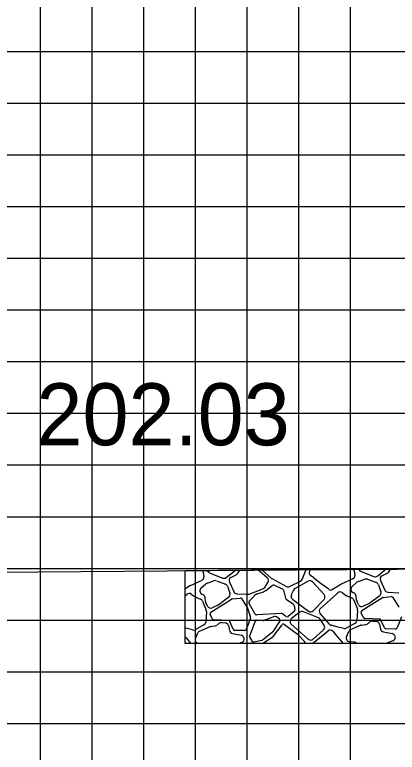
# Model space of a CAD drawing. Extents: x 852922 to 853266, y 364785 to 365005.
# Drawn here: x 853025.74 to 853033.15, y 364866.67 to 364880.95 of the extents above; entities that cross this region are included whole.
import ezdxf

# ---------------------------------------------------------------- set-up
doc = ezdxf.new("R2010")
doc.units = 0
for name, color, linetype in [('D_Roadway_FinishedGrade', 7, 'Continuous'), ('D_Text_Standard', 7, 'Continuous'), ('MAJOR', 7, 'Continuous'), ('MINOR', 7, 'Continuous'), ('S_Roadway_Centerline', 7, 'Continuous')]:
    doc.layers.add(name, color=color, linetype=linetype)

msp = doc.modelspace()

# ---------------------------------------------------------------- linework, layer by layer
at = {"layer": 'D_Roadway_FinishedGrade'}
for p, q in [((853029.394, 364870.158), (853029.404, 364870.066)), ((853029.466, 364870.193), (853029.503, 364870.157)), ((853029.526, 364870.142), (853029.772, 364870.044)), ((853029.84, 364870.055), (853030.016, 364870.198)), ((853030.097, 364870.199), (853030.048, 364870.126)), ((853030.632, 364870.047), (853030.45, 364870.203)), ((853030.527, 364870.204), (853030.71, 364870.043)), ((853031.308, 364870.019), (853031.389, 364870.212)), ((853031.459, 364870.19), (853031.477, 364870.213)), ((853032.319, 364870.187), (853032.328, 364870.096)), ((853032.391, 364870.222), (853032.428, 364870.186)), ((853032.45, 364870.171), (853032.696, 364870.073)), ((853032.765, 364870.084), (853032.941, 364870.228)), ((853033.022, 364870.229), (853032.973, 364870.155)), ((853030.023, 364870.103), (853029.931, 364870.056)), ((853030.723, 364870.035), (853031.004, 364869.884)), ((853031.532, 364870.047), (853031.471, 364870.094)), ((853031.653, 364869.95), (853031.532, 364870.046)), ((853032.288, 364870.027), (853032.066, 364869.925)), ((853032.392, 364869.976), (853032.525, 364870.022)), ((853032.572, 364870.022), (853032.746, 364869.957)), ((853032.947, 364870.132), (853032.856, 364870.085)), ((853029.134, 364869.892), (853029.047, 364869.839)), ((853029.364, 364869.997), (853029.141, 364869.896)), ((853029.349, 364869.848), (853029.444, 364869.933)), ((853029.468, 364869.947), (853029.601, 364869.993)), ((853029.647, 364869.992), (853029.822, 364869.927)), ((853029.862, 364869.886), (853029.909, 364869.752)), ((853029.9, 364869.967), (853029.983, 364869.782)), ((853030.583, 364869.863), (853030.645, 364869.957)), ((853030.605, 364869.805), (853030.731, 364869.902)), ((853030.766, 364869.906), (853030.929, 364869.836)), ((853031.066, 364869.883), (853031.275, 364869.984)), ((853031.424, 364869.984), (853031.171, 364869.841)), ((853031.732, 364869.725), (853031.508, 364869.97)), ((853031.823, 364869.827), (853031.655, 364869.948)), ((853031.972, 364869.868), (853031.898, 364869.824)), ((853032.059, 364869.921), (853031.972, 364869.868)), ((853032.274, 364869.878), (853032.369, 364869.963)), ((853032.787, 364869.915), (853032.834, 364869.781)), ((853032.825, 364869.996), (853032.908, 364869.811)), ((853029.047, 364869.839), (853029.044, 364869.837)), ((853029.048, 364869.705), (853029.076, 364869.729)), ((853029.161, 364869.735), (853029.24, 364869.68)), ((853029.394, 364869.721), (853029.364, 364869.736)), ((853030.043, 364869.742), (853030.255, 364869.732)), ((853030.282, 364869.736), (853030.549, 364869.836)), ((853030.44, 364869.738), (853030.559, 364869.78)), ((853030.949, 364869.813), (853030.989, 364869.656)), ((853031.143, 364869.812), (853031.099, 364869.722)), ((853031.664, 364869.457), (853031.973, 364869.734)), ((853031.973, 364869.734), (853032.001, 364869.759)), ((853032.085, 364869.764), (853032.164, 364869.709)), ((853032.318, 364869.75), (853032.288, 364869.766)), ((853032.967, 364869.771), (853033.18, 364869.761)), ((853029.044, 364869.7), (853029.048, 364869.705)), ((853029.252, 364869.673), (853029.342, 364869.635)), ((853029.378, 364869.599), (853029.453, 364869.421)), ((853029.438, 364869.59), (853029.43, 364869.667)), ((853029.542, 364869.388), (853029.938, 364869.637)), ((853029.886, 364869.675), (853029.703, 364869.534)), ((853029.953, 364869.642), (853030.109, 364869.656)), ((853030.141, 364869.64), (853030.255, 364869.451)), ((853030.284, 364869.595), (853030.371, 364869.691)), ((853031.002, 364869.637), (853031.138, 364869.539)), ((853031.12, 364869.638), (853031.434, 364869.403)), ((853031.525, 364869.411), (853031.732, 364869.633)), ((853032.177, 364869.702), (853032.266, 364869.664)), ((853032.302, 364869.628), (853032.378, 364869.451)), ((853032.363, 364869.62), (853032.355, 364869.696)), ((853032.398, 364869.533), (853032.368, 364869.599)), ((853032.466, 364869.417), (853032.863, 364869.666)), ((853032.811, 364869.704), (853032.628, 364869.563)), ((853032.878, 364869.671), (853033.033, 364869.686)), ((853033.066, 364869.669), (853033.179, 364869.481)), ((853029.473, 364869.503), (853029.444, 364869.57)), ((853029.69, 364869.526), (853029.564, 364869.469)), ((853030.258, 364869.444), (853030.308, 364869.286)), ((853030.4, 364869.349), (853030.28, 364869.555)), ((853031.152, 364869.517), (853031.167, 364869.428)), ((853032.614, 364869.555), (853032.488, 364869.498)), ((853029.459, 364869.389), (853029.443, 364869.193)), ((853029.567, 364869.257), (853029.528, 364869.346)), ((853030.905, 364869.361), (853030.432, 364869.332)), ((853030.771, 364869.301), (853030.569, 364869.223)), ((853030.869, 364869.254), (853030.802, 364869.298)), ((853030.995, 364869.303), (853030.927, 364869.354)), ((853031.154, 364869.395), (853031.037, 364869.304)), ((853031.265, 364869.386), (853031.1, 364869.26)), ((853031.628, 364869.272), (853031.333, 364869.394)), ((853031.837, 364869.152), (853031.657, 364869.362)), ((853032.383, 364869.418), (853032.367, 364869.222)), ((853032.491, 364869.286), (853032.453, 364869.375)), ((853033.232, 364869.293), (853033.149, 364869.08)), ((853029.879, 364869.222), (853029.596, 364869.236)), ((853029.66, 364869.134), (853029.697, 364869.167)), ((853029.748, 364869.183), (853029.821, 364869.176)), ((853029.976, 364869.053), (853029.909, 364869.202)), ((853030.307, 364869.263), (853030.224, 364869.05)), ((853030.397, 364869.21), (853030.291, 364868.923)), ((853030.554, 364869.221), (853030.432, 364869.232)), ((853030.767, 364869.034), (853030.879, 364869.207)), ((853030.967, 364869.147), (853031.236, 364868.946)), ((853031.096, 364869.155), (853031.428, 364868.861)), ((853031.734, 364869.133), (853031.659, 364869.247)), ((853032.332, 364869.168), (853032.162, 364869.075)), ((853032.457, 364869.135), (853032.549, 364869.147)), ((853032.804, 364869.252), (853032.521, 364869.265)), ((853032.584, 364869.163), (853032.622, 364869.196)), ((853032.673, 364869.212), (853032.746, 364869.206)), ((853032.806, 364869.153), (853032.828, 364869.056)), ((853032.901, 364869.082), (853032.833, 364869.232)), ((853029.055, 364869.073), (853029.044, 364869.076)), ((853029.188, 364869.04), (853029.055, 364869.073)), ((853029.407, 364869.139), (853029.238, 364869.046)), ((853029.323, 364869.018), (853029.515, 364869.101)), ((853029.533, 364869.105), (853029.624, 364869.118)), ((853029.882, 364869.124), (853029.904, 364869.027)), ((853030.192, 364869.029), (853030.007, 364869.033)), ((853030.542, 364868.848), (853030.76, 364869.026)), ((853030.75, 364868.914), (853030.919, 364869.14)), ((853031.508, 364868.779), (853031.81, 364869.023)), ((853031.519, 364868.861), (853031.723, 364869.044)), ((853031.979, 364869.103), (853031.872, 364869.13)), ((853031.905, 364869.014), (853031.981, 364868.923)), ((853032.113, 364869.069), (853031.979, 364869.103)), ((853032.167, 364868.906), (853032.211, 364869.012)), ((853032.247, 364869.048), (853032.439, 364869.13)), ((853032.882, 364869.004), (853033.053, 364868.971)), ((853033.116, 364869.058), (853032.931, 364869.062)), ((853029.044, 364868.909), (853029.057, 364868.894)), ((853029.057, 364868.894), (853029.153, 364868.779)), ((853029.242, 364868.877), (853029.287, 364868.982)), ((853029.957, 364868.975), (853030.128, 364868.942)), ((853030.182, 364868.891), (853030.184, 364868.88)), ((853030.294, 364868.894), (853030.334, 364868.827)), ((853030.538, 364868.779), (853030.741, 364868.905)), ((853031.24, 364868.942), (853031.357, 364868.818)), ((853031.981, 364868.923), (853032.102, 364868.779)), ((853033.106, 364868.92), (853033.109, 364868.909)), ((853029.334, 364868.779), (853029.298, 364868.782)), ((853030.141, 364868.799), (853030.086, 364868.779)), ((853030.301, 364868.779), (853030.314, 364868.784)), ((853030.347, 364868.781), (853030.349, 364868.779)), ((853030.37, 364868.811), (853030.526, 364868.841)), ((853032.325, 364868.802), (853032.223, 364868.812)), ((853033.066, 364868.828), (853032.93, 364868.779))]:
    msp.add_line(p, q, dxfattribs=at)
msp.add_lwpolyline([(853038.044, 364868.779), (853029.044, 364868.779), (853029.044, 364870.189), (853038.044, 364870.279)], dxfattribs=at)
for centre, radius, start, end in [((853029.326, 364870.151), 0.0684, 5.7687, 37.1559), ((853029.551, 364870.206), 0.0684, 225.5742, 248.268), ((853031.513, 364870.148), 0.0684, 142.5272, 231.9144), ((853032.251, 364870.18), 0.0684, 5.7687, 37.1559), ((853032.476, 364870.235), 0.0684, 225.5742, 248.268), ((853032.916, 364870.193), 0.0684, 297.1393, 326.3585), ((853029.335, 364870.059), 0.0684, 294.5367, 5.7687), ((853029.797, 364870.108), 0.0684, 248.268, 309.234), ((853029.962, 364869.995), 0.0684, 117.1393, 204.3237), ((853029.992, 364870.164), 0.0684, 297.1393, 326.3585), ((853030.588, 364869.995), 0.0684, 326.5778, 49.4679), ((853030.755, 364870.095), 0.0684, 228.8154, 241.8683), ((853031.245, 364870.046), 0.0684, 295.9781, 337.2187), ((853031.49, 364869.993), 0.0684, 51.4804, 51.9144), ((853032.26, 364870.089), 0.0684, 294.5367, 5.7687), ((853032.548, 364869.958), 0.0684, 69.6007, 109.0092), ((853032.721, 364870.137), 0.0684, 248.268, 309.234), ((853032.887, 364870.024), 0.0684, 117.1393, 204.3237), ((853029.17, 364869.833), 0.0684, 114.5367, 121.2249), ((853029.49, 364869.882), 0.0684, 109.0092, 131.7602), ((853029.623, 364869.928), 0.0684, 69.6007, 109.0092), ((853029.798, 364869.863), 0.0684, 19.3156, 69.6007), ((853030.526, 364869.9), 0.0684, 290.4998, 326.5778), ((853030.752, 364869.875), 0.0342, 66.7141, 127.3386), ((853031.036, 364869.944), 0.0684, 241.8683, 295.9781), ((853031.458, 364869.924), 0.0684, 42.4077, 119.3317), ((853031.695, 364870.004), 0.0684, 231.4804, 234.0454), ((853032.094, 364869.863), 0.0684, 114.5367, 121.2249), ((853032.319, 364869.827), 0.0684, 131.7602, 242.8748), ((853032.414, 364869.912), 0.0684, 109.0092, 131.7602), ((853032.722, 364869.893), 0.0684, 19.3156, 69.6007), ((853029.122, 364869.678), 0.0684, 55.3566, 131.8312), ((853029.395, 364869.797), 0.0684, 131.7602, 242.8748), ((853029.362, 364869.66), 0.0684, 5.7687, 62.8748), ((853029.845, 364869.729), 0.0684, 307.5941, 19.3156), ((853030.046, 364869.81), 0.0684, 204.3237, 267.3497), ((853030.258, 364869.8), 0.0684, 267.3497, 290.4998), ((853030.498, 364869.577), 0.171, 109.7079, 137.8958), ((853030.501, 364869.941), 0.171, 289.7079, 307.3386), ((853030.916, 364869.804), 0.0342, 14.335, 66.7141), ((853031.161, 364869.692), 0.0684, 154.0674, 233.2109), ((853031.204, 364869.782), 0.0684, 119.3317, 154.0674), ((853031.682, 364869.679), 0.0684, 317.0063, 42.4077), ((853031.863, 364869.882), 0.0684, 234.0454, 301.2249), ((853032.046, 364869.708), 0.0684, 55.3566, 131.8312), ((853032.287, 364869.69), 0.0684, 5.7687, 62.8748), ((853032.769, 364869.759), 0.0684, 307.5941, 19.3156), ((853032.97, 364869.84), 0.0684, 204.3237, 267.3497), ((853029.279, 364869.736), 0.0684, 235.3566, 246.9448), ((853029.315, 364869.572), 0.0684, 23.0537, 66.9449), ((853029.506, 364869.597), 0.0684, 185.7687, 203.9594), ((853029.956, 364869.608), 0.0342, 95.2411, 122.1256), ((853030.112, 364869.622), 0.0342, 31.0845, 95.2411), ((853030.309, 364869.572), 0.0342, 137.8958, 210.3662), ((853031.022, 364869.665), 0.0342, 194.335, 234.2606), ((853032.203, 364869.765), 0.0684, 235.3566, 246.9449), ((853032.239, 364869.601), 0.0684, 23.0537, 66.9449), ((853032.431, 364869.627), 0.0684, 185.7687, 203.9594), ((853032.881, 364869.637), 0.0342, 95.2411, 122.1256), ((853033.036, 364869.652), 0.0342, 31.0845, 95.2411), ((853029.536, 364869.531), 0.0684, 203.9594, 294.4344), ((853029.661, 364869.588), 0.0684, 294.4344, 307.5941), ((853030.225, 364869.434), 0.0342, 17.5017, 31.0845), ((853031.118, 364869.511), 0.0342, 9.3204, 54.2606), ((853031.709, 364869.406), 0.0684, 131.8312, 220.5318), ((853032.315, 364869.424), 0.0684, 355.3798, 23.0537), ((853032.46, 364869.56), 0.0684, 203.9594, 294.4344), ((853032.586, 364869.618), 0.0684, 294.4344, 307.5941), ((853029.39, 364869.395), 0.0684, 355.3798, 23.0537), ((853029.56, 364869.359), 0.0342, 122.1256, 203.1941), ((853030.275, 364869.276), 0.0342, 338.7728, 17.5017), ((853030.43, 364869.366), 0.0342, 210.3662, 273.5646), ((853030.783, 364869.269), 0.0342, 56.8842, 111.0577), ((853030.907, 364869.327), 0.0342, 53.0056, 93.5646), ((853031.016, 364869.331), 0.0342, 233.0056, 308.109), ((853031.133, 364869.422), 0.0342, 308.109, 9.3204), ((853031.307, 364869.331), 0.0684, 67.552, 127.1813), ((853031.475, 364869.457), 0.0684, 233.2109, 317.0063), ((853032.484, 364869.388), 0.0342, 122.1256, 203.1941), ((853032.523, 364869.299), 0.0342, 203.1941, 267.2468), ((853029.375, 364869.199), 0.0684, 298.6467, 355.3798), ((853029.598, 364869.27), 0.0342, 203.1941, 267.2468), ((853029.742, 364869.115), 0.0684, 84.8636, 130.9388), ((853029.815, 364869.108), 0.0684, 12.9816, 84.8636), ((853029.878, 364869.188), 0.0342, 24.3237, 87.2468), ((853030.429, 364869.198), 0.0342, 85.002, 159.5814), ((853030.557, 364869.255), 0.0342, 265.002, 291.0577), ((853030.85, 364869.225), 0.0342, 326.8842, 56.8842), ((853030.947, 364869.12), 0.0342, 53.1689, 143.1689), ((853031.142, 364869.206), 0.0684, 127.1813, 228.4518), ((853031.602, 364869.209), 0.0684, 33.5368, 67.552), ((853031.889, 364869.196), 0.0684, 220.5318, 255.8307), ((853032.299, 364869.228), 0.0684, 298.6467, 355.3798), ((853032.539, 364869.215), 0.0684, 277.6992, 310.9388), ((853032.667, 364869.144), 0.0684, 84.8636, 130.9388), ((853032.739, 364869.138), 0.0684, 12.9816, 84.8636), ((853032.802, 364869.218), 0.0342, 24.3237, 87.2468), ((853029.205, 364869.106), 0.0684, 255.8307, 298.6467), ((853029.35, 364868.955), 0.0684, 113.1941, 156.8921), ((853029.542, 364869.038), 0.0684, 97.6992, 113.1941), ((853029.615, 364869.186), 0.0684, 277.6992, 310.9388), ((853029.971, 364869.042), 0.0684, 192.9816, 258.9406), ((853030.007, 364869.067), 0.0342, 204.3237, 268.6964), ((853030.193, 364869.063), 0.0342, 268.6964, 338.7728), ((853030.738, 364869.053), 0.0342, 309.3484, 326.8842), ((853031.677, 364869.095), 0.0684, 311.8205, 33.5368), ((853031.853, 364868.97), 0.0684, 40.0454, 128.9472), ((853032.13, 364869.135), 0.0684, 255.8307, 298.6467), ((853032.274, 364868.985), 0.0684, 113.1941, 156.8921), ((853032.466, 364869.067), 0.0684, 97.6992, 113.1941), ((853032.895, 364869.071), 0.0684, 192.9816, 258.9406), ((853032.932, 364869.096), 0.0342, 204.3237, 268.6964), ((853033.117, 364869.092), 0.0342, 268.6964, 338.7728), ((853029.305, 364868.85), 0.0684, 156.8921, 264.52), ((853030.115, 364868.874), 0.0684, 13.7083, 78.9406), ((853030.118, 364868.863), 0.0684, 289.9802, 13.7083), ((853030.323, 364868.911), 0.0342, 159.5814, 211.2249), ((853030.722, 364868.934), 0.0342, 301.9472, 323.1689), ((853031.215, 364868.919), 0.0342, 43.3633, 53.1689), ((853031.473, 364868.912), 0.0684, 228.4518, 311.8205), ((853032.23, 364868.88), 0.0684, 156.8921, 264.52), ((853033.04, 364868.904), 0.0684, 13.7083, 78.9406), ((853033.042, 364868.893), 0.0684, 289.9802, 13.7083), ((853030.327, 364868.753), 0.0342, 55.0366, 111.7683), ((853030.363, 364868.844), 0.0342, 211.2249, 280.7782), ((853030.52, 364868.874), 0.0342, 280.7782, 309.3484), ((853031.307, 364868.771), 0.0684, 6.2815, 43.3633), ((853032.319, 364868.734), 0.0684, 41.354, 84.52)]:
    msp.add_arc(centre, radius, start, end, dxfattribs=at)
at = {"layer": 'MAJOR'}
for p, q in [((853028.244, 364858.233), (853028.244, 364893.233)), ((852948.244, 364878.233), (853228.244, 364878.233)), ((852948.244, 364873.233), (853228.244, 364873.233)), ((852948.244, 364868.233), (853228.244, 364868.233))]:
    msp.add_line(p, q, dxfattribs=at)
at = {"layer": 'MINOR'}
for p, q in [((853026.244, 364858.233), (853026.244, 364893.233)), ((853027.244, 364858.233), (853027.244, 364893.233)), ((853029.244, 364858.233), (853029.244, 364893.233)), ((853030.244, 364858.233), (853030.244, 364893.233)), ((853031.244, 364858.233), (853031.244, 364893.233)), ((853032.244, 364858.233), (853032.244, 364893.233)), ((852948.244, 364880.233), (853228.244, 364880.233)), ((852948.244, 364879.233), (853228.244, 364879.233)), ((852948.244, 364877.233), (853228.244, 364877.233)), ((852948.244, 364876.233), (853228.244, 364876.233)), ((852948.244, 364875.233), (853228.244, 364875.233)), ((852948.244, 364874.233), (853228.244, 364874.233)), ((852948.244, 364872.233), (853228.244, 364872.233)), ((852948.244, 364871.233), (853228.244, 364871.233)), ((852948.244, 364870.233), (853228.244, 364870.233)), ((852948.244, 364869.233), (853228.244, 364869.233)), ((852948.244, 364867.233), (853228.244, 364867.233))]:
    msp.add_line(p, q, dxfattribs=at)
at = {"layer": 'S_Roadway_Centerline'}
msp.add_lwpolyline([(852948.244, 364867.115), (852952.293, 364867.224), (852982.811, 364869.572), (852983.433, 364869.613), (852984.764, 364869.671), (852995.961, 364869.609), (853002.177, 364870.032), (853019.783, 364870.025), (853022.004, 364870.134), (853031.206, 364870.205), (853040.954, 364870.271), (853047.088, 364870.613), (853061.473, 364871.309), (853080.196, 364872.293), (853086.656, 364872.726), (853095.621, 364874.314), (853108.715, 364876.755), (853119.923, 364878.669), (853126.685, 364878.29), (853138.551, 364878.414), (853139.241, 364878.439), (853141.359, 364878.394), (853158.491, 364878.3)], dxfattribs=at)

# ---------------------------------------------------------------- texts
at = {"layer": 'D_Text_Standard'}
msp.add_text('202.03', height=1.2, dxfattribs=at).set_placement((853026.162, 364872.614))

doc.saveas('drawing.dxf')
